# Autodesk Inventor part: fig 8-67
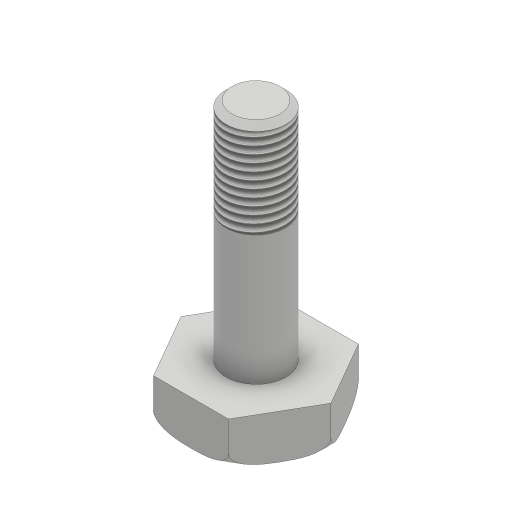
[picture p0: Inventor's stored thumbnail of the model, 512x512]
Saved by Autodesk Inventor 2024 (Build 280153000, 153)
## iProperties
Created: 2016-04
Part Number: fig 8-67
Material: Generic
Document SubType Name: Modeling
Designer: Sandeep
Density: 1 g/cm^3
Appearance: Default
Author: Sandeep
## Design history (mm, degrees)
sketch "Sketch1"
  geometry: C1 r 25 at (0, 0); 1 further point
  constraints: 1 centre point, 1 coincident
  dimensions: "d0" = 50 diameter of C1
extrude "Extrusion1" new body sketch "Sketch1" distance "d1" = 15; taper "d2" = 0 deg
fillet "Fillet1" dims "d3" = 5
sketch "Sketch2"
  geometry: L1 (12.5, 21.651)-(25, 0); L2 (25, 0)-(12.5, -21.651); L3 (12.5, -21.651)-(-12.5, -21.651); L4 (-12.5, -21.651)-(-25, 0); L5 (-25, 0)-(-12.5, 21.651); L6 (-12.5, 21.651)-(12.5, 21.651); 3 further points
  constraints: 12 end point, 1 coincident, 1 horizontal, 15 other
extrude "Extrusion2" cut sketch "Sketch2" distance "d4" = 32.5; taper "d5" = 0 deg
sketch "Sketch3"
  geometry: C1 r 10 at (0, 0); 1 further point
  constraints: 1 centre point, 1 coincident
  dimensions: "d6" = 20 diameter of C1
extrude "Extrusion3" join sketch "Sketch3" distance "d7" = 75; taper "d8" = 0 deg
chamfer "Chamfer1" distance "d9" = 2; stored, may be unused: second distance "d10" = 2, angle "d11" = 45 deg
thread "Thread1" dims "d12" = 30, "d13" = 0
body "Solid1"
